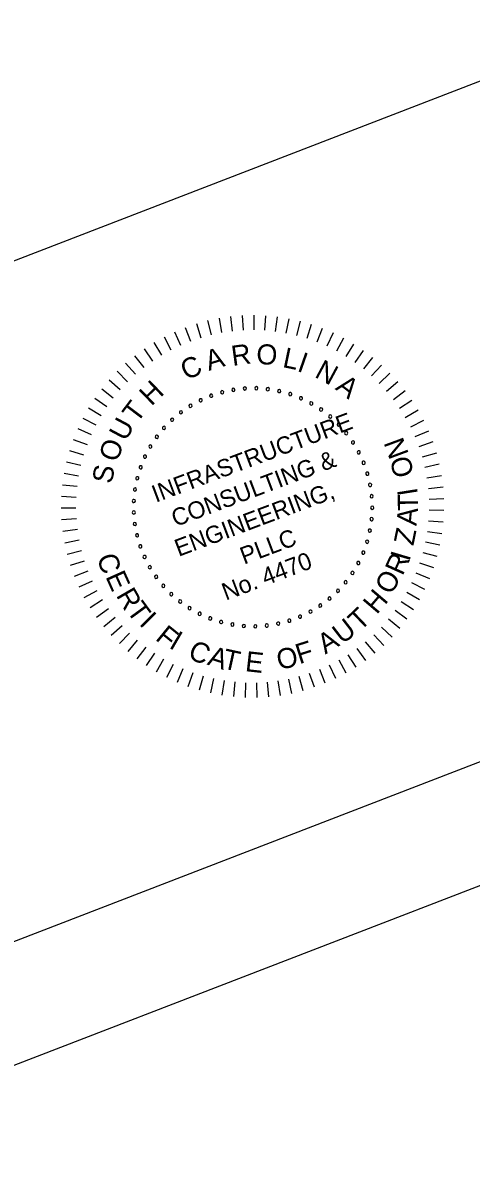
# Model space of a CAD drawing. Extents: x 1971188 to 1971603, y 795903 to 796238.
# Drawn here: x 1971495.88 to 1971515.27, y 795987.28 to 796036.66 of the extents above; entities that cross this region are included whole.
import ezdxf

# ---------------------------------------------------------------- set-up
doc = ezdxf.new("R2010")
doc.units = 0
for name, color, linetype in [('BR_BORDER LINES', 7, 'Continuous'), ('BR_TEXT', 7, 'Continuous'), ('Level 31', 7, 'Continuous')]:
    doc.layers.add(name, color=color, linetype=linetype)

msp = doc.modelspace()

# ---------------------------------------------------------------- linework, layer by layer
at = {"layer": 'BR_BORDER LINES'}
for p, q in [((1971282.272, 795914.531), (1971596.323, 796035.824)), ((1971466.4, 796015.126), (1971516.449, 796034.456))]:
    msp.add_line(p, q, dxfattribs=at)
at = {"layer": 'BR_TEXT'}
for p, q in [((1971504.868, 796023.947), (1971504.942, 796023.315)), ((1971505.372, 796023.99), (1971505.407, 796023.354)), ((1971505.876, 796024.002), (1971505.873, 796023.365)), ((1971506.381, 796023.983), (1971506.338, 796023.348)), ((1971502.91, 796023.474), (1971503.135, 796022.878)), ((1971503.388, 796023.637), (1971503.576, 796023.029)), ((1971503.875, 796023.771), (1971504.025, 796023.152)), ((1971504.369, 796023.874), (1971504.481, 796023.248)), ((1971506.883, 796023.934), (1971506.802, 796023.302)), ((1971507.382, 796023.853), (1971507.262, 796023.228)), ((1971507.874, 796023.743), (1971507.717, 796023.126)), ((1971508.359, 796023.603), (1971508.164, 796022.997)), ((1971501.989, 796023.063), (1971502.284, 796022.499)), ((1971502.443, 796023.283), (1971502.704, 796022.702)), ((1971508.835, 796023.433), (1971508.603, 796022.84)), ((1971509.299, 796023.235), (1971509.032, 796022.657)), ((1971509.75, 796023.009), (1971509.449, 796022.448)), ((1971501.124, 796022.542), (1971501.486, 796022.018)), ((1971501.549, 796022.816), (1971501.878, 796022.271)), ((1971510.187, 796022.756), (1971509.852, 796022.215)), ((1971510.608, 796022.476), (1971510.24, 796021.957)), ((1971500.717, 796022.243), (1971501.11, 796021.742)), ((1971511.01, 796022.172), (1971510.612, 796021.676)), ((1971499.962, 796021.574), (1971500.413, 796021.124)), ((1971500.329, 796021.92), (1971500.752, 796021.444)), ((1971511.394, 796021.843), (1971510.965, 796021.372)), ((1971511.756, 796021.492), (1971511.3, 796021.048)), ((1971499.616, 796021.206), (1971500.094, 796020.785)), ((1971512.097, 796021.12), (1971511.614, 796020.704)), ((1971499.294, 796020.818), (1971499.796, 796020.426)), ((1971512.414, 796020.727), (1971511.907, 796020.341)), ((1971498.995, 796020.41), (1971499.521, 796020.05)), ((1971512.707, 796020.315), (1971512.177, 796019.962)), ((1971498.476, 796019.545), (1971499.041, 796019.252)), ((1971498.723, 796019.986), (1971499.269, 796019.658)), ((1971512.974, 796019.887), (1971512.424, 796019.566)), ((1971498.257, 796019.09), (1971498.839, 796018.832)), ((1971513.214, 796019.443), (1971512.646, 796019.156)), ((1971498.066, 796018.623), (1971498.662, 796018.401)), ((1971513.427, 796018.985), (1971512.842, 796018.734)), ((1971513.612, 796018.515), (1971513.012, 796018.3)), ((1971497.903, 796018.145), (1971498.513, 796017.96)), ((1971513.767, 796018.035), (1971513.156, 796017.857)), ((1971497.771, 796017.658), (1971498.39, 796017.51)), ((1971513.893, 796017.546), (1971513.272, 796017.405)), ((1971497.668, 796017.164), (1971498.295, 796017.054)), ((1971513.989, 796017.051), (1971513.361, 796016.948)), ((1971497.595, 796016.664), (1971498.228, 796016.593)), ((1971514.055, 796016.55), (1971513.421, 796016.486)), ((1971497.553, 796016.161), (1971498.189, 796016.128)), ((1971514.09, 796016.047), (1971513.454, 796016.021)), ((1971497.542, 796015.656), (1971498.179, 796015.662)), ((1971514.094, 796015.542), (1971513.457, 796015.555)), ((1971497.562, 796015.152), (1971498.197, 796015.197)), ((1971514.067, 796015.038), (1971513.433, 796015.09)), ((1971497.612, 796014.649), (1971498.243, 796014.733)), ((1971514.01, 796014.536), (1971513.38, 796014.627)), ((1971497.693, 796014.151), (1971498.318, 796014.273)), ((1971513.922, 796014.039), (1971513.299, 796014.168)), ((1971497.804, 796013.659), (1971498.42, 796013.818)), ((1971513.805, 796013.548), (1971513.19, 796013.715)), ((1971497.945, 796013.174), (1971498.55, 796013.371)), ((1971513.657, 796013.065), (1971513.054, 796013.269)), ((1971498.115, 796012.699), (1971498.707, 796012.932)), ((1971513.48, 796012.592), (1971512.891, 796012.833)), ((1971498.314, 796012.235), (1971498.891, 796012.504)), ((1971513.275, 796012.131), (1971512.701, 796012.407)), ((1971498.541, 796011.783), (1971499.1, 796012.087)), ((1971498.795, 796011.347), (1971499.334, 796011.685)), ((1971513.042, 796011.683), (1971512.486, 796011.993)), ((1971499.075, 796010.927), (1971499.593, 796011.297)), ((1971512.496, 796010.834), (1971511.982, 796011.21)), ((1971512.782, 796011.25), (1971512.246, 796011.594)), ((1971499.38, 796010.525), (1971499.874, 796010.925)), ((1971512.186, 796010.436), (1971511.696, 796010.842)), ((1971499.709, 796010.142), (1971500.178, 796010.572)), ((1971500.06, 796009.78), (1971500.503, 796010.238)), ((1971511.495, 796009.701), (1971511.058, 796010.164)), ((1971511.852, 796010.058), (1971511.387, 796010.493)), ((1971500.434, 796009.44), (1971500.847, 796009.924)), ((1971500.827, 796009.123), (1971501.21, 796009.631)), ((1971511.117, 796009.366), (1971510.709, 796009.855)), ((1971501.238, 796008.831), (1971501.59, 796009.362)), ((1971510.304, 796008.768), (1971509.958, 796009.303)), ((1971510.719, 796009.055), (1971510.342, 796009.567)), ((1971501.667, 796008.565), (1971501.986, 796009.116)), ((1971502.112, 796008.325), (1971502.396, 796008.894)), ((1971502.57, 796008.113), (1971502.819, 796008.698)), ((1971508.963, 796008.068), (1971508.72, 796008.657)), ((1971509.424, 796008.274), (1971509.146, 796008.847)), ((1971509.871, 796008.508), (1971509.559, 796009.063)), ((1971503.04, 796007.929), (1971503.253, 796008.529)), ((1971503.52, 796007.774), (1971503.696, 796008.386)), ((1971504.009, 796007.648), (1971504.148, 796008.27)), ((1971504.505, 796007.553), (1971504.605, 796008.182)), ((1971507.02, 796007.536), (1971506.927, 796008.166)), ((1971507.517, 796007.624), (1971507.385, 796008.247)), ((1971508.007, 796007.743), (1971507.838, 796008.357)), ((1971508.49, 796007.891), (1971508.284, 796008.493)), ((1971505.006, 796007.488), (1971505.067, 796008.122)), ((1971505.509, 796007.454), (1971505.532, 796008.09)), ((1971506.014, 796007.45), (1971505.998, 796008.087)), ((1971506.518, 796007.478), (1971506.464, 796008.112))]:
    msp.add_line(p, q, dxfattribs=at)
for centre, start, end in [((1971504.027, 796020.516), 20.6445, 200.6445), ((1971504.027, 796020.516), 200.6445, 20.6445), ((1971504.501, 796020.668), 15.1061, 195.1061), ((1971504.501, 796020.668), 195.1061, 15.1061), ((1971504.988, 796020.774), 9.5676, 189.5676), ((1971504.988, 796020.774), 189.5676, 9.5676), ((1971505.483, 796020.832), 4.0291, 184.0291), ((1971505.483, 796020.832), 184.0291, 4.0291), ((1971505.981, 796020.842), 358.4907, 178.4907), ((1971505.981, 796020.842), 178.4907, 358.4907), ((1971506.478, 796020.804), 172.9522, 352.9522), ((1971506.478, 796020.804), 352.9522, 172.9522), ((1971506.969, 796020.718), 167.4138, 347.4138), ((1971506.969, 796020.718), 347.4138, 167.4138), ((1971507.449, 796020.585), 161.8753, 341.8753), ((1971507.449, 796020.585), 341.8753, 161.8753), ((1971503.132, 796020.079), 31.7214, 211.7214), ((1971503.132, 796020.079), 211.7214, 31.7214), ((1971503.569, 796020.319), 26.183, 206.183), ((1971503.569, 796020.319), 206.183, 26.183), ((1971507.914, 796020.406), 156.3368, 336.3368), ((1971507.914, 796020.406), 336.3368, 156.3368), ((1971508.36, 796020.183), 150.7984, 330.7984), ((1971508.36, 796020.183), 330.7984, 150.7984), ((1971502.339, 796019.478), 42.7984, 222.7984), ((1971502.339, 796019.478), 222.7984, 42.7984), ((1971502.721, 796019.798), 37.2599, 217.2599), ((1971502.721, 796019.798), 217.2599, 37.2599), ((1971508.782, 796019.919), 145.2599, 325.2599), ((1971508.782, 796019.919), 325.2599, 145.2599), ((1971509.177, 796019.615), 139.7214, 319.7214), ((1971509.177, 796019.615), 319.7214, 139.7214), ((1971501.989, 796019.123), 48.3368, 228.3368), ((1971501.989, 796019.123), 228.3368, 48.3368), ((1971509.541, 796019.274), 134.183, 314.183), ((1971509.541, 796019.274), 314.183, 134.183), ((1971501.676, 796018.735), 53.8753, 233.8753), ((1971501.676, 796018.735), 233.8753, 53.8753), ((1971509.869, 796018.899), 128.6445, 308.6445), ((1971509.869, 796018.899), 308.6445, 128.6445), ((1971510.161, 796018.495), 123.1061, 303.1061), ((1971510.161, 796018.495), 303.1061, 123.1061), ((1971501.401, 796018.32), 59.4138, 239.4138), ((1971501.401, 796018.32), 239.4138, 59.4138), ((1971510.411, 796018.064), 117.5676, 297.5676), ((1971510.411, 796018.064), 297.5676, 117.5676), ((1971501.167, 796017.879), 64.9522, 244.9522), ((1971501.167, 796017.879), 244.9522, 64.9522), ((1971510.62, 796017.612), 112.0291, 292.0291), ((1971510.62, 796017.612), 292.0291, 112.0291), ((1971500.978, 796017.419), 70.4907, 250.4907), ((1971500.978, 796017.419), 250.4907, 70.4907), ((1971510.783, 796017.141), 106.4907, 286.4907), ((1971510.783, 796017.141), 286.4907, 106.4907), ((1971500.833, 796016.942), 76.0291, 256.0291), ((1971500.833, 796016.942), 256.0291, 76.0291), ((1971510.9, 796016.657), 100.9522, 280.9522), ((1971510.9, 796016.657), 280.9522, 100.9522), ((1971500.735, 796016.453), 81.5676, 261.5676), ((1971500.735, 796016.453), 261.5676, 81.5676), ((1971510.97, 796016.163), 95.4138, 275.4138), ((1971510.97, 796016.163), 275.4138, 95.4138), ((1971500.685, 796015.957), 87.1061, 267.1061), ((1971500.685, 796015.957), 267.1061, 87.1061), ((1971510.992, 796015.665), 89.8753, 269.8753), ((1971510.992, 796015.665), 269.8753, 89.8753), ((1971500.683, 796015.459), 92.6445, 272.6445), ((1971500.683, 796015.459), 272.6445, 92.6445), ((1971510.966, 796015.168), 84.3368, 264.3368), ((1971510.966, 796015.168), 264.3368, 84.3368), ((1971500.729, 796014.963), 98.183, 278.183), ((1971500.729, 796014.963), 278.183, 98.183), ((1971510.892, 796014.675), 78.7984, 258.7984), ((1971510.892, 796014.675), 258.7984, 78.7984), ((1971500.823, 796014.474), 103.7214, 283.7214), ((1971500.823, 796014.474), 283.7214, 103.7214), ((1971510.771, 796014.192), 73.2599, 253.2599), ((1971510.771, 796014.192), 253.2599, 73.2599), ((1971500.963, 796013.995), 109.2599, 289.2599), ((1971500.963, 796013.995), 289.2599, 109.2599), ((1971501.149, 796013.533), 114.7984, 294.7984), ((1971501.149, 796013.533), 294.7984, 114.7984), ((1971510.603, 796013.722), 67.7214, 247.7214), ((1971510.603, 796013.722), 247.7214, 67.7214), ((1971501.379, 796013.091), 120.3368, 300.3368), ((1971501.379, 796013.091), 300.3368, 120.3368), ((1971510.391, 796013.271), 62.183, 242.183), ((1971510.391, 796013.271), 242.183, 62.183), ((1971501.65, 796012.673), 125.8753, 305.8753), ((1971501.65, 796012.673), 305.8753, 125.8753), ((1971510.137, 796012.843), 56.6445, 236.6445), ((1971510.137, 796012.843), 236.6445, 56.6445), ((1971501.961, 796012.283), 131.4138, 311.4138), ((1971501.961, 796012.283), 311.4138, 131.4138), ((1971509.511, 796012.069), 45.5676, 225.5676), ((1971509.511, 796012.069), 225.5676, 45.5676), ((1971509.843, 796012.441), 51.1061, 231.1061), ((1971509.843, 796012.441), 231.1061, 51.1061), ((1971502.307, 796011.925), 136.9522, 316.9522), ((1971502.307, 796011.925), 316.9522, 136.9522), ((1971502.687, 796011.602), 142.4907, 322.4907), ((1971502.687, 796011.602), 322.4907, 142.4907), ((1971509.144, 796011.731), 40.0291, 220.0291), ((1971509.144, 796011.731), 220.0291, 40.0291), ((1971503.096, 796011.317), 148.0291, 328.0291), ((1971503.096, 796011.317), 328.0291, 148.0291), ((1971503.53, 796011.074), 333.5676, 153.5676), ((1971508.323, 796011.169), 28.9522, 208.9522), ((1971508.323, 796011.169), 208.9522, 28.9522), ((1971508.747, 796011.431), 34.4907, 214.4907), ((1971508.747, 796011.431), 214.4907, 34.4907), ((1971503.53, 796011.074), 153.5676, 333.5676), ((1971503.986, 796010.873), 159.1061, 339.1061), ((1971503.986, 796010.873), 339.1061, 159.1061), ((1971504.46, 796010.717), 164.6445, 344.6445), ((1971504.46, 796010.717), 344.6445, 164.6445), ((1971504.946, 796010.607), 170.183, 350.183), ((1971504.946, 796010.607), 350.183, 170.183), ((1971505.44, 796010.545), 355.7214, 175.7214), ((1971506.435, 796010.565), 6.7984, 186.7984), ((1971506.927, 796010.647), 12.3368, 192.3368), ((1971506.927, 796010.647), 192.3368, 12.3368), ((1971507.408, 796010.776), 17.8753, 197.8753), ((1971507.408, 796010.776), 197.8753, 17.8753), ((1971507.875, 796010.95), 23.4138, 203.4138), ((1971507.875, 796010.95), 203.4138, 23.4138), ((1971505.44, 796010.545), 175.7214, 355.7214), ((1971505.938, 796010.531), 1.2599, 181.2599), ((1971505.938, 796010.531), 181.2599, 1.2599), ((1971506.435, 796010.565), 186.7984, 6.7984)]:
    msp.add_arc(centre, 0.0701, start, end, dxfattribs=at)
at = {"layer": 'Level 31'}
msp.add_lwpolyline([(1971266.971, 795903.262), (1971602.794, 796032.965), (1971523.531, 796238.19), (1971187.708, 796108.487)], close=True, dxfattribs=at)

# ---------------------------------------------------------------- texts
at = {"layer": 'BR_TEXT'}
for s, height, rotation, p in [('A', 0.872, 16.8158, (1971503.924, 796021.586)), ('R', 0.872, 7.7858, (1971504.958, 796021.804)), ('O', 0.872, 358.7557, (1971505.977, 796021.878)), ('L', 0.872, 348.2257, (1971507.081, 796021.763)), ('C', 0.872, 25.8458, (1971502.967, 796021.164)), ('I', 0.872, 340.6957, (1971507.707, 796021.6)), ('N', 0.872, 331.6657, (1971508.458, 796021.345)), ('H', 0.872, 43.9059, (1971501.44, 796020.044)), ('A', 0.872, 322.6356, (1971509.361, 796020.811)), ('T', 0.872, 52.9359, (1971500.82, 796019.294)), ('U', 0.872, 61.9659, (1971500.338, 796018.506)), ('INFRASTRUCTURE', 0.74771, 20.6445, (1971501.634, 796015.88)), ('O', 0.872, 70.9959, (1971499.969, 796017.603)), ('N', 0.872, 110.3262, (1971512.585, 796017.996)), ('CONSULTING &', 0.74771, 20.6445, (1971502.482, 796014.829)), ('O', 0.872, 104.3262, (1971512.811, 796017.103)), ('S', 0.872, 80.026, (1971499.734, 796016.674)), ('ENGINEERING,', 0.74771, 20.6445, (1971502.621, 796013.538)), ('I', 0.872, 99.0269, (1971512.97, 796016.26)), ('T', 0.872, 90.5131, (1971512.974, 796015.538)), ('A', 0.872, 84.5131, (1971512.904, 796014.864)), ('PLLC', 0.7477, 20.6445, (1971505.45, 796013.198)), ('Z', 0.872, 78.5131, (1971512.77, 796013.994)), ('C', 0.872, 288.1427, (1971499.074, 796013.525)), ('No. 4470', 0.7477, 20.6445, (1971504.663, 796011.641)), ('R', 0.872, 65.6445, (1971512.304, 796012.689)), ('I', 0.872, 73.4516, (1971512.594, 796013.308)), ('E', 0.872, 294.1427, (1971499.445, 796012.687)), ('O', 0.872, 59.6445, (1971511.806, 796011.854)), ('R', 0.872, 300.1427, (1971499.896, 796011.872)), ('H', 0.872, 49.6445, (1971511.186, 796011.014)), ('T', 0.872, 306.1427, (1971500.343, 796011.2)), ('I', 0.872, 314.889, (1971500.883, 796010.625)), ('T', 0.872, 43.6445, (1971510.467, 796010.289)), ('U', 0.872, 37.6445, (1971509.699, 796009.731)), ('F', 0.872, 320.889, (1971501.577, 796009.97)), ('I', 0.872, 329.6445, (1971502.164, 796009.62)), ('A', 0.872, 31.6445, (1971508.965, 796009.303)), ('C', 0.872, 335.6445, (1971502.97, 796009.18)), ('F', 0.872, 17.6445, (1971507.841, 796008.886)), ('A', 0.872, 341.6445, (1971503.826, 796008.882)), ('T', 0.872, 347.6445, (1971504.473, 796008.719)), ('E', 0.872, 353.6445, (1971505.472, 796008.593)), ('O', 0.872, 11.6445, (1971506.955, 796008.642))]:
    msp.add_text(s, height=height, rotation=rotation, dxfattribs=at).set_placement(p)

doc.saveas('drawing.dxf')
